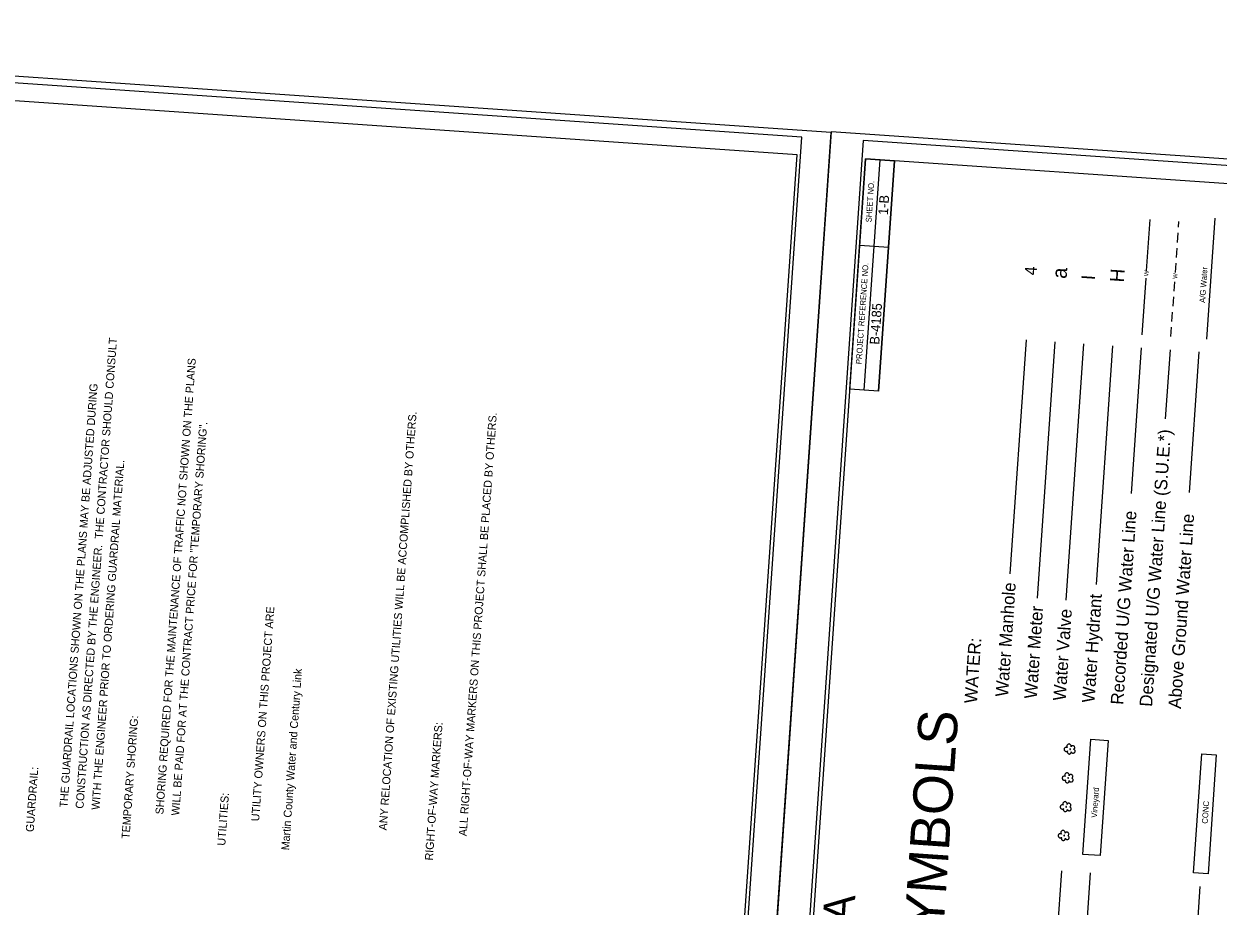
# Model space of a CAD drawing. Extents: x 2598107 to 2605763, y 726018 to 731166.
# Drawn here: x 2602035 to 2603897, y 729620 to 730995 of the extents above; entities that cross this region are included whole.
import ezdxf

# ---------------------------------------------------------------- set-up
doc = ezdxf.new("R2010")
doc.units = 0
for name, color, linetype in [('Prop EOT', 7, 'Continuous'), ('Sheet Cutting Line CELL', 7, 'Continuous'), ('Sheet Plan CELL', 7, 'Continuous'), ('Sheet Plot Border Inside CELL', 7, 'Continuous'), ('Sheet Plot Border Outside CELL', 7, 'Continuous'), ('Sheet Symbology CELL', 7, 'Continuous')]:
    doc.layers.add(name, color=color, linetype=linetype)

msp = doc.modelspace()

# ---------------------------------------------------------------- linework, layer by layer
at = {"layer": 'Sheet Cutting Line CELL'}
for p, q in [((2603294, 730826.7), (2603033.6, 727046.7)), ((2603033.6, 727046.7), (2603293.9, 730825.6))]:
    msp.add_line(p, q, dxfattribs=at)
at = {"layer": 'Sheet Plan CELL'}
msp.add_lwpolyline([(2600883.8, 730953.3), (2600651.9, 727586.2), (2603008.9, 727423.9), (2603240.7, 730790.9)], close=True, dxfattribs=at)
at = {"layer": 'Sheet Plot Border Inside CELL'}
for points in [[(2602990.7, 727079), (2603248.3, 730818.6), (2600880.2, 730981.7), (2600622.6, 727242.1)], [(2605454.4, 726909.3), (2605712, 730650.1), (2603343.7, 730813.2), (2603086, 727072.4)]]:
    msp.add_lwpolyline(points, close=True, dxfattribs=at)
at = {"layer": 'Sheet Plot Border Outside CELL'}
for points in [[(2603033.6, 727046.7), (2603293.9, 730825.6), (2600836, 730994.9), (2600575.7, 727216)], [(2605502.8, 726876.6), (2605763.1, 730656.7), (2603294, 730826.7), (2603033.6, 727046.7)]]:
    msp.add_lwpolyline(points, close=True, dxfattribs=at)
at = {"layer": 'Sheet Symbology CELL'}
for p, q in [((2603345.2, 730423.9), (2603370, 730783.2)), ((2603367.7, 730422.4), (2603392.4, 730781.6)), ((2603785.3, 730609.9), (2603790.9, 730690)), ((2603835.1, 730678.1), (2603835.8, 730686.9)), ((2603879.5, 730503.5), (2603892.5, 730692.1)), ((2603833.5, 730654.5), (2603834.5, 730669.1)), ((2603338.3, 730650), (2603383.2, 730646.9)), ((2603831.9, 730630.9), (2603832.9, 730645.5)), ((2603830.3, 730607.4), (2603831.3, 730622)), ((2603778.5, 730510.4), (2603784.6, 730598.7)), ((2603828.3, 730578.4), (2603829.3, 730593)), ((2603826.7, 730554.9), (2603827.7, 730569.4)), ((2603825, 730531.3), (2603826, 730545.9)), ((2603823.4, 730507.7), (2603824.4, 730522.3)), ((2603597.5, 730502.6), (2603572.4, 730138.1)), ((2603642.4, 730499.5), (2603614.9, 730099.9)), ((2603687.3, 730496.4), (2603659.8, 730096.8)), ((2603732.2, 730493.3), (2603706.6, 730121.2)), ((2603777.1, 730490.2), (2603761.5, 730263.2)), ((2603822, 730487.1), (2603814.6, 730379.3)), ((2603866.9, 730484), (2603851.8, 730264.7)), ((2603652.7, 729675.1), (2603621, 729215.1)), ((2603697.6, 729672), (2603665.9, 729212)), ((2603868.5, 729650.5), (2603855.5, 729461))]:
    msp.add_line(p, q, dxfattribs=at)
for points in [[(2603347.4, 730784.7), (2603115.6, 727417.7), (2605470.2, 727255.5), (2605702.1, 730622.6)], [(2603322.7, 730425.5), (2603347.4, 730784.7), (2603392.4, 730781.6), (2603367.7, 730422.4)]]:
    msp.add_lwpolyline(points, close=True, dxfattribs=at)
for points in [[(2603662, 729867.2), (2603661.3, 729867.6), (2603660.6, 729867.7), (2603660, 729867.7), (2603659.3, 729867.6), (2603658.7, 729867.3), (2603658.1, 729867), (2603657.6, 729866.5), (2603657.2, 729865.9), (2603657, 729865.2), (2603656.9, 729864.6), (2603657, 729863.9), (2603657.2, 729863.2), (2603657.5, 729862.6), (2603657.9, 729862), (2603658.5, 729861.7), (2603659.1, 729861.4), (2603659.7, 729861.2), (2603660.4, 729861.2), (2603661.1, 729861.3), (2603661.7, 729861.6), (2603662.4, 729862), (2603662, 729861.4), (2603661.8, 729860.8), (2603661.8, 729860.1), (2603662, 729859.5), (2603662.2, 729858.9), (2603662.6, 729858.3), (2603663, 729857.9), (2603663.5, 729857.5), (2603664.1, 729857.3), (2603664.9, 729857.2), (2603665.4, 729857.2), (2603666, 729857.4), (2603666.6, 729857.8), (2603667.1, 729858.1), (2603667.5, 729858.7), (2603667.8, 729859.3), (2603668, 729859.9), (2603668, 729860.6), (2603668.2, 729860), (2603668.6, 729859.4), (2603669.1, 729859), (2603669.7, 729858.7), (2603670.4, 729858.5), (2603670.9, 729858.4), (2603671.6, 729858.5), (2603672.2, 729858.8), (2603672.8, 729859.1), (2603673.3, 729859.5), (2603673.6, 729860.1), (2603673.9, 729860.6), (2603673.9, 729861.3), (2603674, 729861.9), (2603673.9, 729862.5), (2603673.5, 729863.1), (2603673.2, 729863.7), (2603672.2, 729864.3)], [(2603672.2, 729864.3), (2603673.1, 729865.6), (2603673.4, 729866.3), (2603673.5, 729866.9), (2603673.5, 729867.6), (2603673.3, 729868.2), (2603673, 729868.8), (2603672.6, 729869.4), (2603672.1, 729869.8), (2603671.5, 729870), (2603670.8, 729870.3), (2603670.2, 729870.2), (2603669.5, 729870.2), (2603668.8, 729869.8), (2603668.3, 729869.4), (2603667.9, 729868.9), (2603667.6, 729868.3), (2603667.7, 729868.9), (2603667.8, 729869.7), (2603667.6, 729870.3), (2603667.3, 729871), (2603667, 729871.6), (2603666.5, 729872.1), (2603665.8, 729872.4), (2603665.1, 729872.6), (2603664.5, 729872.8), (2603663.8, 729872.7), (2603663.1, 729872.5), (2603662.5, 729872.1), (2603661.9, 729871.6), (2603661.5, 729871), (2603661.3, 729870.4), (2603661.1, 729869.7), (2603661.1, 729869), (2603661.2, 729868.4), (2603661.5, 729867.8), (2603662, 729867.2)], [(2603665.7, 729865), (2603665.7, 729864.7), (2603665.8, 729864.4), (2603665.9, 729864.2), (2603666.3, 729864.2), (2603666.5, 729864.2), (2603666.7, 729864.4), (2603666.7, 729864.7), (2603666.8, 729864.9), (2603666.5, 729865.2), (2603666.2, 729865.3), (2603666, 729865.2), (2603665.7, 729865)], [(2603686, 729700.8), (2603698.4, 729880.3), (2603725.3, 729878.5), (2603712.9, 729698.9), (2603686, 729700.8)], [(2603858.7, 729672.2), (2603871.5, 729857.3), (2603893.9, 729855.8), (2603881.2, 729670.6), (2603858.7, 729672.2)], [(2603669.1, 729819.4), (2603670, 729820.7), (2603670.3, 729821.4), (2603670.5, 729822), (2603670.4, 729822.7), (2603670.2, 729823.3), (2603669.9, 729823.9), (2603669.5, 729824.5), (2603669, 729824.9), (2603668.4, 729825.1), (2603667.8, 729825.4), (2603667.1, 729825.3), (2603666.4, 729825.3), (2603665.7, 729824.9), (2603665.2, 729824.6), (2603664.8, 729824), (2603664.5, 729823.4), (2603664.6, 729824), (2603664.7, 729824.8), (2603664.5, 729825.4), (2603664.2, 729826.1), (2603663.9, 729826.7), (2603663.4, 729827.2), (2603662.7, 729827.5), (2603662.1, 729827.7), (2603661.4, 729827.9), (2603660.7, 729827.8), (2603660, 729827.6), (2603659.4, 729827.2), (2603658.8, 729826.7), (2603658.4, 729826.1), (2603658.2, 729825.5), (2603658, 729824.8), (2603658, 729824.1), (2603658.2, 729823.5), (2603658.4, 729822.9), (2603658.9, 729822.3)], [(2603658.9, 729822.3), (2603658.2, 729822.7), (2603657.5, 729822.8), (2603656.9, 729822.8), (2603656.2, 729822.7), (2603655.6, 729822.4), (2603655, 729822.1), (2603654.5, 729821.6), (2603654.1, 729821), (2603653.9, 729820.3), (2603653.8, 729819.7), (2603653.9, 729819), (2603654.1, 729818.3), (2603654.4, 729817.7), (2603654.8, 729817.2), (2603655.4, 729816.8), (2603656, 729816.5), (2603656.6, 729816.3), (2603657.3, 729816.3), (2603658, 729816.4), (2603658.6, 729816.7), (2603659.3, 729817.1), (2603658.9, 729816.5), (2603658.8, 729815.9), (2603658.7, 729815.2), (2603658.9, 729814.6), (2603659.1, 729814), (2603659.5, 729813.4), (2603659.9, 729813), (2603660.4, 729812.6), (2603661, 729812.4), (2603661.8, 729812.3), (2603662.3, 729812.3), (2603662.9, 729812.5), (2603663.5, 729812.9), (2603664, 729813.2), (2603664.4, 729813.8), (2603664.7, 729814.4), (2603664.9, 729815), (2603664.9, 729815.7), (2603665.1, 729815.1), (2603665.5, 729814.5), (2603666, 729814.1), (2603666.6, 729813.9), (2603667.3, 729813.6), (2603667.8, 729813.5), (2603668.5, 729813.6), (2603669.1, 729813.9), (2603669.7, 729814.2), (2603670.2, 729814.6), (2603670.5, 729815.2), (2603670.8, 729815.7), (2603670.9, 729816.4), (2603670.9, 729817.1), (2603670.8, 729817.6), (2603670.4, 729818.2), (2603670.1, 729818.8), (2603669.1, 729819.4)], [(2603662.7, 729820.1), (2603662.6, 729819.8), (2603662.7, 729819.5), (2603662.8, 729819.3), (2603663.2, 729819.3), (2603663.4, 729819.3), (2603663.6, 729819.5), (2603663.6, 729819.8), (2603663.7, 729820), (2603663.5, 729820.3), (2603663.1, 729820.4), (2603662.9, 729820.3), (2603662.7, 729820.1)], [(2603655.8, 729777.4), (2603655.1, 729777.8), (2603654.5, 729777.9), (2603653.8, 729777.9), (2603653.1, 729777.8), (2603652.5, 729777.5), (2603651.9, 729777.2), (2603651.4, 729776.7), (2603651.1, 729776.1), (2603650.8, 729775.4), (2603650.7, 729774.8), (2603650.8, 729774.1), (2603651, 729773.4), (2603651.3, 729772.8), (2603651.7, 729772.3), (2603652.3, 729771.9), (2603652.9, 729771.6), (2603653.6, 729771.5), (2603654.2, 729771.4), (2603654.9, 729771.5), (2603655.5, 729771.8), (2603656.2, 729772.2), (2603655.8, 729771.6), (2603655.7, 729771), (2603655.6, 729770.3), (2603655.8, 729769.7), (2603656, 729769.1), (2603656.4, 729768.5), (2603656.8, 729768.1), (2603657.4, 729767.7), (2603657.9, 729767.5), (2603658.7, 729767.4), (2603659.3, 729767.5), (2603659.8, 729767.6), (2603660.4, 729768), (2603660.9, 729768.4), (2603661.3, 729768.9), (2603661.7, 729769.5), (2603661.8, 729770.1), (2603661.9, 729770.8), (2603662, 729770.2), (2603662.4, 729769.6), (2603662.9, 729769.2), (2603663.5, 729769), (2603664.2, 729768.7), (2603664.7, 729768.7), (2603665.4, 729768.7), (2603666, 729769), (2603666.6, 729769.3), (2603667.1, 729769.7), (2603667.5, 729770.3), (2603667.7, 729770.8), (2603667.8, 729771.5), (2603667.8, 729772.2), (2603667.7, 729772.7), (2603667.3, 729773.3), (2603667, 729773.9), (2603666.1, 729774.5)], [(2603666.1, 729774.5), (2603666.9, 729775.8), (2603667.2, 729776.5), (2603667.4, 729777.2), (2603667.3, 729777.8), (2603667.1, 729778.4), (2603666.8, 729779), (2603666.4, 729779.6), (2603665.9, 729780), (2603665.3, 729780.2), (2603664.7, 729780.5), (2603664, 729780.4), (2603663.3, 729780.4), (2603662.6, 729780), (2603662.1, 729779.7), (2603661.7, 729779.1), (2603661.4, 729778.5), (2603661.5, 729779.1), (2603661.6, 729779.9), (2603661.4, 729780.5), (2603661.1, 729781.2), (2603660.8, 729781.8), (2603660.3, 729782.3), (2603659.6, 729782.6), (2603659, 729782.8), (2603658.3, 729783), (2603657.6, 729782.9), (2603656.9, 729782.7), (2603656.3, 729782.3), (2603655.7, 729781.8), (2603655.4, 729781.3), (2603655.1, 729780.6), (2603654.9, 729779.9), (2603654.9, 729779.3), (2603655.1, 729778.6), (2603655.4, 729778), (2603655.8, 729777.4)], [(2603659.6, 729775.2), (2603659.5, 729774.9), (2603659.6, 729774.6), (2603659.7, 729774.4), (2603660.1, 729774.4), (2603660.3, 729774.4), (2603660.5, 729774.6), (2603660.6, 729774.9), (2603660.6, 729775.1), (2603660.4, 729775.4), (2603660, 729775.5), (2603659.8, 729775.4), (2603659.6, 729775.2)], [(2603663, 729729.6), (2603663.8, 729730.9), (2603664.1, 729731.6), (2603664.3, 729732.3), (2603664.2, 729732.9), (2603664, 729733.5), (2603663.7, 729734.1), (2603663.3, 729734.7), (2603662.8, 729735.1), (2603662.2, 729735.3), (2603661.6, 729735.6), (2603660.9, 729735.5), (2603660.2, 729735.5), (2603659.5, 729735.1), (2603659, 729734.8), (2603658.7, 729734.2), (2603658.3, 729733.6), (2603658.4, 729734.2), (2603658.5, 729735), (2603658.3, 729735.6), (2603658, 729736.3), (2603657.7, 729736.9), (2603657.2, 729737.4), (2603656.5, 729737.8), (2603655.9, 729737.9), (2603655.2, 729738.1), (2603654.5, 729738), (2603653.8, 729737.8), (2603653.2, 729737.4), (2603652.6, 729736.9), (2603652.3, 729736.4), (2603652, 729735.7), (2603651.8, 729735), (2603651.8, 729734.4), (2603652, 729733.7), (2603652.3, 729733.1), (2603652.7, 729732.5)], [(2603652.7, 729732.5), (2603652, 729732.9), (2603651.4, 729733), (2603650.7, 729733), (2603650, 729732.9), (2603649.4, 729732.6), (2603648.8, 729732.3), (2603648.3, 729731.8), (2603648, 729731.2), (2603647.7, 729730.5), (2603647.6, 729729.9), (2603647.7, 729729.2), (2603647.9, 729728.5), (2603648.2, 729728), (2603648.6, 729727.4), (2603649.3, 729727), (2603649.8, 729726.7), (2603650.5, 729726.6), (2603651.1, 729726.5), (2603651.8, 729726.6), (2603652.4, 729726.9), (2603653.1, 729727.3), (2603652.7, 729726.7), (2603652.6, 729726.1), (2603652.5, 729725.4), (2603652.7, 729724.8), (2603652.9, 729724.2), (2603653.3, 729723.7), (2603653.7, 729723.2), (2603654.3, 729722.8), (2603654.8, 729722.6), (2603655.6, 729722.5), (2603656.2, 729722.6), (2603656.7, 729722.7), (2603657.3, 729723.2), (2603657.8, 729723.5), (2603658.2, 729724), (2603658.6, 729724.6), (2603658.7, 729725.2), (2603658.8, 729725.9), (2603658.9, 729725.3), (2603659.4, 729724.7), (2603659.8, 729724.3), (2603660.4, 729724.1), (2603661.1, 729723.8), (2603661.7, 729723.8), (2603662.3, 729723.8), (2603662.9, 729724.1), (2603663.5, 729724.4), (2603664, 729724.8), (2603664.4, 729725.4), (2603664.6, 729725.9), (2603664.7, 729726.6), (2603664.7, 729727.3), (2603664.6, 729727.8), (2603664.2, 729728.4), (2603663.9, 729729), (2603663, 729729.6)], [(2603656.5, 729730.3), (2603656.4, 729730), (2603656.5, 729729.7), (2603656.6, 729729.5), (2603657, 729729.5), (2603657.2, 729729.5), (2603657.4, 729729.7), (2603657.5, 729730), (2603657.5, 729730.2), (2603657.3, 729730.5), (2603656.9, 729730.6), (2603656.7, 729730.5), (2603656.5, 729730.3)]]:
    msp.add_lwpolyline(points, dxfattribs=at)

# ---------------------------------------------------------------- texts
at = {"layer": 'Prop EOT'}
for s, height, rotation, p in [('1-B', 15, 86.0601, (2603382.1, 730696.7)), ('B-4185', 15, 86.0601, (2603368.7, 730494.7)), ('         CONSTRUCTION AS DIRECTED BY THE ENGINEER.  THE CONTRACTOR SHOULD CONSULT', 12.474, 85.9164, (2602125.3, 729730)), ('         SHORING REQUIRED FOR THE MAINTENANCE OF TRAFFIC NOT SHOWN ON THE PLANS ', 12.474, 85.9164, (2602249.8, 729721.1)), ('         THE GUARDRAIL LOCATIONS SHOWN ON THE PLANS MAY BE ADJUSTED DURING ', 12.474, 85.9164, (2602100.4, 729731.7)), ('         ANY RELOCATION OF EXISTING UTILITIES WILL BE ACCOMPLISHED BY OTHERS.  ', 12.474, 85.9164, (2602598.1, 729696.2)), ('         ALL RIGHT-OF-WAY MARKERS ON THIS PROJECT SHALL BE PLACED BY OTHERS.  ', 12.474, 85.9164, (2602722.6, 729687.3)), ('         WILL BE PAID FOR AT THE CONTRACT PRICE FOR "TEMPORARY SHORING".', 12.474, 85.9164, (2602274.6, 729719.3)), ('         WITH THE ENGINEER PRIOR TO ORDERING GUARDRAIL MATERIAL.', 12.474, 85.9164, (2602150.2, 729728.2)), ('         UTILITY OWNERS ON THIS PROJECT ARE ', 12.474, 85.9164, (2602399.1, 729710.4)), ('Martin County Water and Century Link', 12.474, 85.9164, (2602448.8, 729706.9)), ('TEMPORARY SHORING:  ', 12.474, 85.9164, (2602200, 729724.6)), ('RIGHT-OF-WAY MARKERS:  ', 12.474, 85.9164, (2602672.8, 729690.9)), ('GUARDRAIL:  ', 12.474, 85.9164, (2602050.7, 729735.3)), ('UTILITIES:  ', 12.474, 85.9164, (2602349.3, 729714))]:
    msp.add_text(s, height=height, rotation=rotation, dxfattribs=at).set_placement(p)
at = {"layer": 'Sheet Symbology CELL'}
for s, height, p in [('SHEET NO.', 9, (2603356.5, 730685.4)), ('PROJECT REFERENCE NO.', 9, (2603341.1, 730464.3)), ('4', 18.6, (2603613.7, 730602.7)), ('a', 23, (2603660.7, 730597.3)), ('H', 21.9, (2603750, 730591.6)), ('W', 6.75, (2603788.2, 730601.6)), ('A/G Water', 9, (2603876.6, 730559.9)), ('I', 21.1, (2603704.7, 730595.2)), ('W', 6.75, (2603833, 730597.5)), ('Designated U/G Water Line (S.U.E.*)', 19.688, (2603793.9, 729930.4)), ('Recorded U/G Water Line', 19.688, (2603749, 729933.5)), ('Above Ground Water Line', 19.688, (2603838.8, 729927.3)), ('Water Manhole', 19.688, (2603569.4, 729945.9)), ('Water Hydrant', 19.688, (2603704.1, 729936.6)), ('Water Meter', 19.688, (2603614.3, 729942.8)), ('Water Valve', 19.688, (2603659.2, 729939.7)), ('WATER:', 19.69, (2603520.9, 729935.6)), ('CONVENTIONAL  PLAN SHEET SYMBOLS', 61.201, (2603380.9, 728308.3)), ('Vineyard', 9, (2603708, 729757.5)), ('CONC', 9, (2603880.6, 729748.3)), ('STATE OF NORTH CAROLINA', 48.193, (2603269, 728729.4))]:
    msp.add_text(s, height=height, rotation=86.0601, dxfattribs=at).set_placement(p)

doc.saveas('drawing.dxf')
